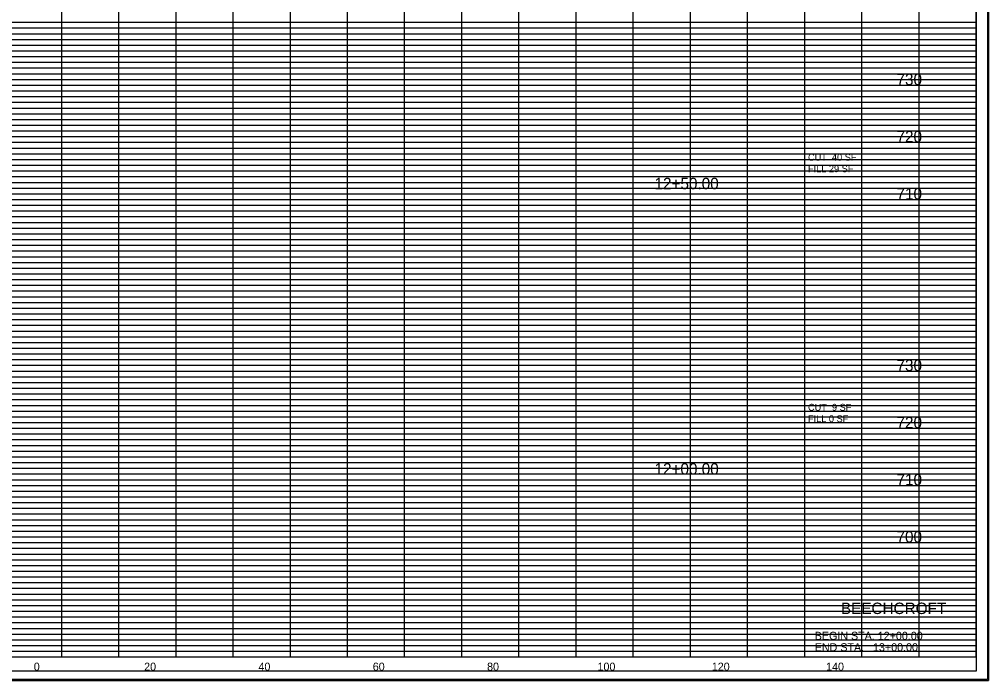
# Model space of a CAD drawing. Extents: x -200 to 1704, y -325 to 2307.
# Drawn here: x 1152.6 to 1322.2, y 995.9 to 1111.5 of the extents above; entities that cross this region are included whole.
import ezdxf

# ---------------------------------------------------------------- set-up
doc = ezdxf.new("R2010")
doc.units = 0
for name, color, linetype in [('DESIGN - SHEET - Corner Text', 7, 'Continuous'), ('DESIGN - SHEET - Light Grid', 7, 'Continuous'), ('DESIGN - SHEET - Linework', 7, 'Continuous'), ('DESIGN - SHEET - Plot Shape', 7, 'Continuous'), ('DESIGN - TYPICAL - Text', 7, 'Continuous')]:
    doc.layers.add(name, color=color, linetype=linetype)

msp = doc.modelspace()

# ---------------------------------------------------------------- linework, layer by layer
at = {"layer": 'DESIGN - SHEET - Light Grid'}
for p, q in [((1080, 1111), (1160, 1111)), ((1160, 1111), (1240, 1111)), ((1240, 1111), (1320, 1111)), ((1080, 1109), (1160, 1109)), ((1080, 1108), (1160, 1108)), ((1160, 1109), (1240, 1109)), ((1160, 1108), (1240, 1108)), ((1240, 1109), (1320, 1109)), ((1240, 1108), (1320, 1108)), ((1080, 1107), (1160, 1107)), ((1080, 1106), (1160, 1106)), ((1160, 1107), (1240, 1107)), ((1160, 1106), (1240, 1106)), ((1240, 1107), (1320, 1107)), ((1240, 1106), (1320, 1106)), ((1080, 1105), (1160, 1105)), ((1080, 1104), (1160, 1104)), ((1160, 1105), (1240, 1105)), ((1160, 1104), (1240, 1104)), ((1240, 1105), (1320, 1105)), ((1240, 1104), (1320, 1104)), ((1080, 1103), (1160, 1103)), ((1160, 1103), (1240, 1103)), ((1240, 1103), (1320, 1103)), ((1080, 1102), (1160, 1102)), ((1080, 1101), (1160, 1101)), ((1160, 1102), (1240, 1102)), ((1160, 1101), (1240, 1101)), ((1240, 1102), (1320, 1102)), ((1240, 1101), (1320, 1101)), ((1080, 1099), (1160, 1099)), ((1160, 1099), (1240, 1099)), ((1240, 1099), (1320, 1099)), ((1080, 1098), (1160, 1098)), ((1160, 1098), (1240, 1098)), ((1240, 1098), (1320, 1098)), ((1080, 1097), (1160, 1097)), ((1080, 1096), (1160, 1096)), ((1160, 1097), (1240, 1097)), ((1160, 1096), (1240, 1096)), ((1240, 1097), (1320, 1097)), ((1240, 1096), (1320, 1096)), ((1080, 1095), (1160, 1095)), ((1080, 1094), (1160, 1094)), ((1160, 1095), (1240, 1095)), ((1160, 1094), (1240, 1094)), ((1240, 1095), (1320, 1095)), ((1240, 1094), (1320, 1094)), ((1080, 1093), (1160, 1093)), ((1160, 1093), (1240, 1093)), ((1240, 1093), (1320, 1093)), ((1080, 1092), (1160, 1092)), ((1080, 1091), (1160, 1091)), ((1160, 1092), (1240, 1092)), ((1160, 1091), (1240, 1091)), ((1240, 1092), (1320, 1092)), ((1240, 1091), (1320, 1091)), ((1080, 1089), (1160, 1089)), ((1160, 1089), (1240, 1089)), ((1240, 1089), (1320, 1089)), ((1080, 1088), (1160, 1088)), ((1160, 1088), (1240, 1088)), ((1240, 1088), (1320, 1088)), ((1080, 1087), (1160, 1087)), ((1080, 1086), (1160, 1086)), ((1160, 1087), (1240, 1087)), ((1160, 1086), (1240, 1086)), ((1240, 1087), (1320, 1087)), ((1240, 1086), (1320, 1086)), ((1080, 1085), (1160, 1085)), ((1080, 1084), (1160, 1084)), ((1160, 1085), (1240, 1085)), ((1160, 1084), (1240, 1084)), ((1240, 1085), (1320, 1085)), ((1240, 1084), (1320, 1084)), ((1080, 1083), (1160, 1083)), ((1080, 1082), (1160, 1082)), ((1160, 1083), (1240, 1083)), ((1160, 1082), (1240, 1082)), ((1240, 1083), (1320, 1083)), ((1240, 1082), (1320, 1082)), ((1080, 1081), (1160, 1081)), ((1160, 1081), (1240, 1081)), ((1240, 1081), (1320, 1081)), ((1080, 1079), (1160, 1079)), ((1160, 1079), (1240, 1079)), ((1240, 1079), (1320, 1079)), ((1080, 1078), (1160, 1078)), ((1080, 1077), (1160, 1077)), ((1160, 1078), (1240, 1078)), ((1160, 1077), (1240, 1077)), ((1240, 1078), (1320, 1078)), ((1240, 1077), (1320, 1077)), ((1080, 1076), (1160, 1076)), ((1160, 1076), (1240, 1076)), ((1240, 1076), (1320, 1076)), ((1080, 1075), (1160, 1075)), ((1080, 1074), (1160, 1074)), ((1160, 1075), (1240, 1075)), ((1160, 1074), (1240, 1074)), ((1240, 1075), (1320, 1075)), ((1240, 1074), (1320, 1074)), ((1080, 1073), (1160, 1073)), ((1080, 1072), (1160, 1072)), ((1160, 1073), (1240, 1073)), ((1160, 1072), (1240, 1072)), ((1240, 1073), (1320, 1073)), ((1240, 1072), (1320, 1072)), ((1080, 1071), (1160, 1071)), ((1160, 1071), (1240, 1071)), ((1240, 1071), (1320, 1071)), ((1080, 1069), (1160, 1069)), ((1160, 1069), (1240, 1069)), ((1240, 1069), (1320, 1069)), ((1080, 1068), (1160, 1068)), ((1080, 1067), (1160, 1067)), ((1160, 1068), (1240, 1068)), ((1160, 1067), (1240, 1067)), ((1240, 1068), (1320, 1068)), ((1240, 1067), (1320, 1067)), ((1080, 1066), (1160, 1066)), ((1080, 1065), (1160, 1065)), ((1160, 1066), (1240, 1066)), ((1160, 1065), (1240, 1065)), ((1240, 1066), (1320, 1066)), ((1240, 1065), (1320, 1065)), ((1080, 1064), (1160, 1064)), ((1160, 1064), (1240, 1064)), ((1240, 1064), (1320, 1064)), ((1080, 1063), (1160, 1063)), ((1080, 1062), (1160, 1062)), ((1160, 1063), (1240, 1063)), ((1160, 1062), (1240, 1062)), ((1240, 1063), (1320, 1063)), ((1240, 1062), (1320, 1062)), ((1080, 1061), (1160, 1061)), ((1160, 1061), (1240, 1061)), ((1240, 1061), (1320, 1061)), ((1080, 1059), (1160, 1059)), ((1160, 1059), (1240, 1059)), ((1240, 1059), (1320, 1059)), ((1080, 1058), (1160, 1058)), ((1080, 1057), (1160, 1057)), ((1160, 1058), (1240, 1058)), ((1160, 1057), (1240, 1057)), ((1240, 1058), (1320, 1058)), ((1240, 1057), (1320, 1057)), ((1080, 1056), (1160, 1056)), ((1080, 1055), (1160, 1055)), ((1160, 1056), (1240, 1056)), ((1160, 1055), (1240, 1055)), ((1240, 1056), (1320, 1056)), ((1240, 1055), (1320, 1055)), ((1080, 1054), (1160, 1054)), ((1160, 1054), (1240, 1054)), ((1240, 1054), (1320, 1054)), ((1080, 1053), (1160, 1053)), ((1080, 1052), (1160, 1052)), ((1160, 1053), (1240, 1053)), ((1160, 1052), (1240, 1052)), ((1240, 1053), (1320, 1053)), ((1240, 1052), (1320, 1052)), ((1080, 1051), (1160, 1051)), ((1160, 1051), (1240, 1051)), ((1240, 1051), (1320, 1051)), ((1080, 1049), (1160, 1049)), ((1160, 1049), (1240, 1049)), ((1240, 1049), (1320, 1049)), ((1080, 1048), (1160, 1048)), ((1080, 1047), (1160, 1047)), ((1160, 1048), (1240, 1048)), ((1160, 1047), (1240, 1047)), ((1240, 1048), (1320, 1048)), ((1240, 1047), (1320, 1047)), ((1080, 1046), (1160, 1046)), ((1080, 1045), (1160, 1045)), ((1160, 1046), (1240, 1046)), ((1160, 1045), (1240, 1045)), ((1240, 1046), (1320, 1046)), ((1240, 1045), (1320, 1045)), ((1080, 1044), (1160, 1044)), ((1080, 1043), (1160, 1043)), ((1160, 1044), (1240, 1044)), ((1160, 1043), (1240, 1043)), ((1240, 1044), (1320, 1044)), ((1240, 1043), (1320, 1043)), ((1080, 1042), (1160, 1042)), ((1160, 1042), (1240, 1042)), ((1240, 1042), (1320, 1042)), ((1080, 1041), (1160, 1041)), ((1160, 1041), (1240, 1041)), ((1240, 1041), (1320, 1041)), ((1080, 1039), (1160, 1039)), ((1080, 1038), (1160, 1038)), ((1160, 1039), (1240, 1039)), ((1160, 1038), (1240, 1038)), ((1240, 1039), (1320, 1039)), ((1240, 1038), (1320, 1038)), ((1080, 1037), (1160, 1037)), ((1160, 1037), (1240, 1037)), ((1240, 1037), (1320, 1037)), ((1080, 1036), (1160, 1036)), ((1080, 1035), (1160, 1035)), ((1160, 1036), (1240, 1036)), ((1160, 1035), (1240, 1035)), ((1240, 1036), (1320, 1036)), ((1240, 1035), (1320, 1035)), ((1080, 1034), (1160, 1034)), ((1080, 1033), (1160, 1033)), ((1160, 1034), (1240, 1034)), ((1160, 1033), (1240, 1033)), ((1240, 1034), (1320, 1034)), ((1240, 1033), (1320, 1033)), ((1080, 1032), (1160, 1032)), ((1160, 1032), (1240, 1032)), ((1240, 1032), (1320, 1032)), ((1080, 1031), (1160, 1031)), ((1160, 1031), (1240, 1031)), ((1240, 1031), (1320, 1031)), ((1080, 1029), (1160, 1029)), ((1080, 1028), (1160, 1028)), ((1160, 1029), (1240, 1029)), ((1160, 1028), (1240, 1028)), ((1240, 1029), (1320, 1029)), ((1240, 1028), (1320, 1028)), ((1080, 1027), (1160, 1027)), ((1080, 1026), (1160, 1026)), ((1160, 1027), (1240, 1027)), ((1160, 1026), (1240, 1026)), ((1240, 1027), (1320, 1027)), ((1240, 1026), (1320, 1026)), ((1080, 1025), (1160, 1025)), ((1160, 1025), (1240, 1025)), ((1240, 1025), (1320, 1025)), ((1080, 1024), (1160, 1024)), ((1080, 1023), (1160, 1023)), ((1160, 1024), (1240, 1024)), ((1160, 1023), (1240, 1023)), ((1240, 1024), (1320, 1024)), ((1240, 1023), (1320, 1023)), ((1080, 1022), (1160, 1022)), ((1080, 1021), (1160, 1021)), ((1160, 1022), (1240, 1022)), ((1160, 1021), (1240, 1021)), ((1240, 1022), (1320, 1022)), ((1240, 1021), (1320, 1021)), ((1080, 1019), (1160, 1019)), ((1080, 1018), (1160, 1018)), ((1160, 1019), (1240, 1019)), ((1160, 1018), (1240, 1018)), ((1240, 1019), (1320, 1019)), ((1240, 1018), (1320, 1018)), ((1080, 1017), (1160, 1017)), ((1080, 1016), (1160, 1016)), ((1160, 1017), (1240, 1017)), ((1160, 1016), (1240, 1016)), ((1240, 1017), (1320, 1017)), ((1240, 1016), (1320, 1016)), ((1080, 1015), (1160, 1015)), ((1160, 1015), (1240, 1015)), ((1240, 1015), (1320, 1015)), ((1080, 1014), (1160, 1014)), ((1080, 1013), (1160, 1013)), ((1160, 1014), (1240, 1014)), ((1160, 1013), (1240, 1013)), ((1240, 1014), (1320, 1014)), ((1240, 1013), (1320, 1013)), ((1080, 1012), (1160, 1012)), ((1080, 1011), (1160, 1011)), ((1160, 1012), (1240, 1012)), ((1160, 1011), (1240, 1011)), ((1240, 1012), (1320, 1012)), ((1240, 1011), (1320, 1011)), ((1080, 1009), (1160, 1009)), ((1080, 1008), (1160, 1008)), ((1160, 1009), (1240, 1009)), ((1160, 1008), (1240, 1008)), ((1240, 1009), (1320, 1009)), ((1240, 1008), (1320, 1008)), ((1080, 1007), (1160, 1007)), ((1080, 1006), (1160, 1006)), ((1160, 1007), (1240, 1007)), ((1160, 1006), (1240, 1006)), ((1240, 1007), (1320, 1007)), ((1240, 1006), (1320, 1006)), ((1080, 1005), (1160, 1005)), ((1080, 1004), (1160, 1004)), ((1160, 1005), (1240, 1005)), ((1160, 1004), (1240, 1004)), ((1240, 1005), (1320, 1005)), ((1240, 1004), (1320, 1004)), ((1080, 1003), (1160, 1003)), ((1160, 1003), (1240, 1003)), ((1240, 1003), (1320, 1003)), ((1080, 1002), (1160, 1002)), ((1080, 1001), (1160, 1001)), ((1160, 1002), (1240, 1002)), ((1160, 1001), (1240, 1001)), ((1240, 1002), (1320, 1002)), ((1240, 1001), (1320, 1001))]:
    msp.add_line(p, q, dxfattribs=at)
at = {"layer": 'DESIGN - SHEET - Linework'}
for p, q in [((1322.17, 1214.14), (1322.17, 995.86)), ((1160, 1000), (1160, 1210)), ((1170, 1000), (1170, 1210)), ((1180, 1000), (1180, 1210)), ((1190, 1000), (1190, 1210)), ((1200, 1000), (1200, 1210)), ((1210, 1000), (1210, 1210)), ((1220, 1000), (1220, 1210)), ((1230, 1000), (1230, 1210)), ((1240, 1000), (1240, 1210)), ((1250, 1000), (1250, 1210)), ((1260, 1000), (1260, 1210)), ((1270, 1000), (1270, 1210)), ((1280, 1000), (1280, 1200)), ((1290, 1000), (1290, 1200)), ((1300, 1000), (1300, 1200)), ((1310, 1000), (1310, 1200)), ((1000, 1110), (1320, 1110)), ((1000, 1100), (1320, 1100)), ((1000, 1090), (1320, 1090)), ((1000, 1080), (1320, 1080)), ((1000, 1070), (1320, 1070)), ((1000, 1060), (1320, 1060)), ((1000, 1050), (1320, 1050)), ((1000, 1040), (1320, 1040)), ((1000, 1030), (1320, 1030)), ((1000, 1020), (1320, 1020)), ((1000, 1010), (1320, 1010)), ((981.77, 995.86), (1322.17, 995.86))]:
    msp.add_line(p, q, dxfattribs=at)
msp.add_lwpolyline([(1000, 1210), (1000, 1000), (1320, 1000), (1320, 1210), (1000, 1210)], dxfattribs=at)
at = {"layer": 'DESIGN - SHEET - Plot Shape'}
for points in [[(981.97, 1213.94), (1321.97, 1213.94), (1321.97, 996.06), (981.97, 996.06)], [(991.5, 1210), (1320, 1210), (1320, 997.5), (991.5, 997.5)]]:
    msp.add_lwpolyline(points, close=True, dxfattribs=at)

# ---------------------------------------------------------------- texts
at = {"layer": 'DESIGN - SHEET - Corner Text'}
for s, height, p in [('BEECHCROFT ', 2, (1296.33, 1007.5)), ('BEGIN STA. 12+00.00', 1.4, (1291.75, 1003)), ('END STA.   13+00.00', 1.4, (1291.75, 1001))]:
    msp.add_text(s, height=height, dxfattribs=at).set_placement(p)
at = {"layer": 'DESIGN - TYPICAL - Text'}
for s, height, p in [('     730     ', 2, (1302.34, 1100)), ('     720     ', 2, (1302.34, 1090)), ('CUT  40 SF', 1.2, (1290.57, 1086.78)), ('FILL 29 SF', 1.2, (1290.57, 1084.78)), ('     12+50.00     ', 2, (1260, 1081.8)), ('     710     ', 2, (1302.34, 1080)), ('     730     ', 2, (1302.34, 1050)), ('CUT  9 SF', 1.2, (1290.57, 1043.06)), ('FILL 0 SF', 1.2, (1290.57, 1041.06)), ('     720     ', 2, (1302.34, 1040)), ('     12+00.00     ', 2, (1260, 1031.88)), ('     710     ', 2, (1302.34, 1030)), ('     700     ', 2, (1302.34, 1020)), ('     0     ', 1.4, (1152.51, 997.6)), ('     20     ', 1.4, (1171.82, 997.6)), ('     40     ', 1.4, (1191.82, 997.6)), ('     60     ', 1.4, (1211.82, 997.6)), ('     80     ', 1.4, (1231.82, 997.6)), ('     100     ', 1.4, (1251.14, 997.6)), ('     120     ', 1.4, (1271.14, 997.6)), ('     140     ', 1.4, (1291.14, 997.6))]:
    msp.add_text(s, height=height, dxfattribs=at).set_placement(p)

doc.saveas('drawing.dxf')
